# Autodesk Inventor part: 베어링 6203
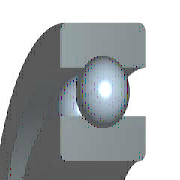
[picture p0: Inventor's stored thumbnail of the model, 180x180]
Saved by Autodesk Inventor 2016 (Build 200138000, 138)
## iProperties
IsCustomPart: 0
Created: 2014-10
Part Number: 베어링 6203
Material: 강철, 연강
Description: 깊은 그루브 볼 베어링
Document SubType Name: Modeling
Standard: KS B 2023
Designer: KYOUNG IL JANG
Standards Organization: KS
Language: ko-KR
Size Designation: 6203 - 17 x 40 x 12
Categories: <MemberInstance><Categories><Category DisplayName="샤프트 부품" InternalName="7f7aeb1f-a693-4053-b835-cee3144e0d98" Mnemonic="SHFT"><Category DisplayName="베어링" Inter
Density: 7.86 g/cm^3
Mass: 64.9809 g
Surface Area: 64.3582 cm^2
Volume: 8.26729 cm^3
Appearance: 노란색
Author: SeoGD™ [www.esajin.kr]
Revision Number: 1
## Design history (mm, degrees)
sketch "스케치" dims "d0" = 5.98 (= -0.26 x WD + 0.26 x BD)
  geometry: L1 (3.01, 14.25)-(8.99, 14.25); L2 (6, 14.25)-(6, 11.26); L3 (6, 14.25)-(6, 17.24); L4 (3.778, 12.249)-(0, 12.249); L5 (0, 8.5)-(12, 8.5); L6 (3.778, 16.251)-(0, 16.251); L7 (0, 20)-(12, 20); L8 (12, 8.5)-(12, 12.249); L9 (8.222, 12.249)-(12, 12.249); L10 (8.222, 16.251)-(12, 16.251); L11 (12, 20)-(12, 16.251); L12 (-1.4, 0)-(8.4, 0) reference; L13 (0, -0.3)-(0, 5.3) reference
  constraints: 22 end point, 4 point on line, 2 collinear, 2 perpendicular, 2 symmetric about line, 1 midpoint, 1 parallel, 14 other
  dimensions: "d9" = 17 diameter of L5 L12 (= WD); "d11" = 40 diameter of L7 L12 (= BD); "d12" = 12 distance between parallel lines of L8 L13 (= KB); "d13" = 24.498 diameter of L9 L12 (= 0.326 x BD + 0.674 x WD)
revolve "본체" stored, may be unused: angle "d6" = 90 deg
revolve "볼" stored, may be unused: angle "d7" = 90 deg
pattern_circular "IDS_ARRAYBALL[SIMPL:T]" dims angle "d3" = 360 deg
body "Solid1"
fillet "모깎기1" dims "d1" = 0.6 (= KRS)
other parameters: "WD" = 17 [user parameter; used in 5 equation terms], "BD" = 40 [user parameter; used in 5 equation terms], "KB" = 12 [user parameter; used in 1 equation term], "KRS" = 0.6 [user parameter; used in 1 equation term], "d4" = 0, "d5" = 0, "d8" = 0, "d14" = 0, "d15" = 0, "BBA" = 0 [user parameter], "BC0" = 4750000 [user parameter], "BC" = 9560000 [user parameter], "WR" = 8.5 (= 0.5 x WD) [user parameter]
